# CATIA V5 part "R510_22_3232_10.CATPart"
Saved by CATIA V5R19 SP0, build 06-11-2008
Material "Steel": density 7860 kg/m3, Young's modulus 2e+11 Pa, Poisson ratio 0.266, thermal expansion 1.17e-05 1/K
Bounding box of the stored display mesh (mm): x -15.868 to 15.969, y -16.07 to 15.873, z 0 to 100
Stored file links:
  G:\Podręcznik\CD\Narzędzia\Arkusz Excel\Modele narzędzi\R510.22-3232-10.CATPart
  C:\Program Files\Dassault Systemes\B19\intel_a\startup\materials\Catalog.CATMaterial
  F:\OSTATNIE\DesignTable2.xls
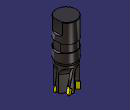
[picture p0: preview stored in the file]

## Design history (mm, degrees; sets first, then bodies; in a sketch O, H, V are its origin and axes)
Parameters
  CuttingType = "CUTTER"
  d = 32 mm {design table}
  D = 32 mm {design table}
  L = 100 mm {design table}
  l = 60 mm {design table}
  alfa = 11 deg {design table}
  gammap = 9 deg {design table}
  S = 3.18 mm {design table}
  epsilon = 85 deg {design table}
  lp = 10 mm {design table}
  x = 0.1131 mm {design table}
  gammaf = -12 deg {design table}
  z = 5 {design table}
  teta = 72 deg {design table}
  `lp'` = 9.8769 mm {design table}
  `lp''` = 5.8466 mm {design table}
Body1 "BODY" (main body), material "Steel"
  Sketch1 "sketch" on yz-plane, origin (0, 0, 0), H (0, 1, 0), V (0, 0, 1)
    line L1 (0, 2.0776) -> (15, 0.2358)
    line L2 (15, 0.2358) -> (15, 40)
    point P3 (15, 40)
    line L3 (15, 40) -> (15, 40)
    point P4 (16, 40)
    line L4 (16, 43.4583) -> (16, 58)
    point P5 (16, 58)
    line L5 (16, 58) -> (15, 58)
    line L6 (15, 58) -> (15, 70)
    line L7 (15, 70) -> (16, 70)
    point P8 (16, 70)
    line L8 (16, 70) -> (16, 99.2929)
    line L9 (16, 99.2929) -> (15.2929, 100)
    line L10 (15.2929, 100) -> (0, 100)
    point P11 (0, 100)
    line L11 (0, 100) -> (0, 2.0776)
    construction line L12 (0, -29.1199) -> (0, 199.3445)
    point P12 (0, -29.1199)
    construction line L13 (0, 0.1131) -> (16, 0.1131)
    point P14 (0, 0.1131)
    point P15 (16, 0.1131)
    construction line L14 (0, 2.0776) -> (16, 0.1131)
    axis line L15 (16, 0.1131) -> (16, -5.5625)
    line L16 (15, 40) -> (16, 43.4583)
    point P17 (15, 40)
    length L6 = 12 {= 0.2*l}
    distance P3 H = 40 {= L-l}
    length L9 = 1
    angle L8 L9 = 45
    distance L6 L8 = 1
    distance L8 L11 = 16 {= d/2}
    length L13 = 16 {= D/2}
    distance H L13 = 0.1131 {= x}
    distance L10 L7 = 30 {= 0.5*l}
    distance P15 L2 = 1
    distance P4 P5 = 18 {= 0.3*l}
    length L16 = 3.6 {= 0.2*(0.3*l)}
    angle L1 L2 = 83
    vertical: L2 V, L4 V, L6 V, L8 V, L11 V, L12 V, L15 V
    horizontal: L3 H, L5 H, L7 H, L10 H, L13 H
    coincidence: P8 L4, P11 V, P12 V, L1 L14, P14 L12, L3 P4, L4 P4, P3 P17
  Shaft1: profile Sketch1, axis Z axis, angle 360
  Fillet1: radius 1.6 {= 0.1*D/2}, on edge [face of Shaft1 from Sketch1.L1 | face of Shaft1 from Sketch1.L2]
  Sketch2 on zx-plane, origin (0, 0, 0), H (-1, 0, 0), V (0, 0, 1)
    line L1 (-14, 100) -> (-14, 82)
    line L2 (-14, 82) -> (-16, 80)
    line L3 (-16, 80) -> (-16, 72)
    line L4 (-16, 72) -> (-14, 70)
    point P5 (-14, 70)
    line L5 (-14, 70) -> (-14, 58)
    line L6 (-14, 58) -> (-16, 56)
    point P7 (-16, 56)
    line L7 (-16, 56) -> (-16, 56)
    line L8 (-16, 56) -> (-19, 56)
    line L9 (-19, 56) -> (-19, 100)
    line L10 (-19, 100) -> (-14, 100)
    reference projected line E1 through (0, 0) direction (0, 1) from axis of face of Shaft1 from Sketch1.L8
    reference projected line E2 (-9.2929, 100) -> (9.2929, 100) from edge [face of Shaft1 from Sketch1.L9 | face of Shaft1 from Sketch1.L10]
    distance L3 E1 = 16 {= d/2}
    distance L1 L3 = 2
    angle L2 L3 = 45
    angle L4 L3 = 45
    length L5 = 12 {= l*0.2}
    length L1 = 18 {= 0.3*l}
    distance P5 L10 = 30 {= 0.5*l}
    distance L9 L1 = 5
    distance L7 L5 = 2
    angle L5 L6 = 45
    vertical: L1 V, L3 V, L5 V, L7 V, L9 V
    horizontal: L8 H, L10 H
    coincidence: L10 E2, L1 L5, P7 L8
  Pocket1: profile Sketch2, direction (0, -1, 0), length 8, mirrored extent
  Plane1: type Angle, Angle 150, Direction Z axis, RefPlane yz-plane
  Plane2: type Offset, Offset 1, RefPlane Plane1, reversed
  Sketch3 "gammap_os_obrotu" on Plane2, origin (0.866, -0.5, 0), H (-0.5, -0.866, 0), V (0, 0, 1)
    line L1 (1.3076, 0) -> (-0.9434, 0)
    reference intersected line E1 through (0, 0) direction (-1, 0) from xy-plane
    horizontal: L1 H
    coincidence: E1 L1
  Plane3 "gammap": type Angle, Angle -9 {= -gammap}, Direction Sketch3, RefPlane Plane2
  Plane4: type Offset, Offset 0.5, RefPlane Plane3, reversed
  Sketch4 on Plane4, origin (1.2725, -0.7347, 0.2327), H (-0.5, -0.866, 0), V (-0.1355, 0.0782, 0.9877)
    line L1 (-16, -2.3223) -> (-16, 6.2448)
    distance V L1 = 16 {= D/2}
  Plane5 "gammaf": type Angle, Angle 12 {= -gammaf}, Direction Sketch4, RefPlane Plane4
  Plane6: type Offset, Offset 0.5, RefPlane Plane5
  Plane7: type Angle, Angle 90, Direction Sketch4, RefPlane Plane5
  Sketch5 on Plane7, origin (4.6982, 14.5939, -0.5486), H (0.9503, -0.3114, 0), V (0.0101, 0.0309, 0.9995)
    point P1 (4.8413, 0.5489)
    line L1 (4.8413, 0.5489) -> (1.6042, 0.6729)
    line L2 (1.6042, 0.6729) -> (0.2625, 9.3333)
    line L3 (0.2625, 9.3333) -> (3.3104, 10.431)
    line L4 (3.3104, 10.431) -> (4.8413, 0.5489)
    reference projected line E1 (5.1594, -1.5042) -> (3.8478, 6.9619) from Sketch4
    construction line L5 (3.3104, 10.431) -> (-1.5922, 9.6715)
    axis line L6 (4.8413, 0.5489) -> (1.1512, -0.0228)
    reference intersected line E2 through (-0.0001, 0.5489) direction (-1, 0) from xy-plane
    distance L2 L4 = 3.18 {= S}
    length L4 = 10 {= lp}
    angle L5 L3 = 11 {= alfa}
    angle L6 L1 = 11 {= alfa}
    coincidence: L4 E1, P1 E2
    perpendicularity: L5 L2
    parallelism: L6 L5
  Plane8: type Offset, Offset 16 {= D/2}, RefPlane Plane1, reversed
  Sketch6 on Plane8, origin (13.8564, -8, 0), H (-0.5, -0.866, 0), V (0, 0, 1)
    line L1 (-9.5247, -3) -> (-9.5247, 26.3474)
    arc A1 centre (-21.5247, 26.3474) radius 12 from (-9.5247, 26.3474) to (-16, 37) ccw
    point P4 (-16, 37)
    line L2 (-16, 37) -> (-16, -3)
    point P5 (-16, -3)
    line L3 (-16, -3) -> (-9.5247, -3)
    axis line L4 (-16, -3) -> (-9.5247, -2.4335)
    point P6 (-16, -3)
    point P7 (-9.5247, -2.4335)
    reference projected line E1 (-9, 40) -> (9, 40) from edge [face of Shaft1 from Sketch1.L2 | face of Shaft1 from Sketch1.L16]
    distance L2 V = 16 {= D/2}
    angle L4 L2 = 85 {= epsilon}
    distance E1 P4 = 3
    radius A1 = 12
    distance H L3 = 3
    length L4 = 6.5 {= 0.65*lp}
    vertical: L1 V, L2 V
    horizontal: L3 H
    tangency: L1 A1
    coincidence: P6 P5, P7 L1
  Pocket2: profile Sketch6, direction (-0.866, 0.5, 0), up to Plane6
  CircPattern1: of Pocket2, instances 5 {= z}, angular step 72 {= teta}, axis from Z axis
  Sketch7 on Plane5, origin (4.4973, -1.4261, 0.7803), H (-0.3066, -0.9518, 0), V (-0.1456, 0.0469, 0.9882)
    line L1 (-15.6327, 9.205) -> (-9.6759, 9.9244)
    point P1 (-15.6327, 9.205)
    reference projected point E1 (-15.6327, 9.205) from vertex [element of Sketch5 | element of Sketch5]
    reference projected line E2 (-15.2936, -1.0922) -> (-15.6227, 8.9024) from Sketch5.L4
    length L1 = 6 {= 0.6*lp}
    angle E2 L1 = 85 {= epsilon}
    coincidence: P1 E1
  Slot1: profile Sketch5, centre curve Sketch7
  CircPattern2: of Slot1, instances 5 {= z}, angular step 72 {= teta}, axis from Z axis
Body2 "INSERTS"
  Sketch8 "CUT" on yz-plane, origin (0, 0, 0), H (0, 1, 0), V (0, 0, 1)
    line L1 (10.1757, 0.5096) -> (16, 0)
    point P2 (16, 0)
    line L2 (16, 0) -> (16, 9.8769)
    line L3 (16, 9.8769) -> (10.1757, 10.3864)
    line L4 (10.1757, 10.3864) -> (10.1757, 0.5096)
    angle L3 L4 = 85
    length L2 = 9.8769 {= `lp'`}
    length L1 = 5.8466 {= `lp''`}
    distance L2 V = 16 {= D/2}
    vertical: L2 V, L4 V
    parallelism: L3 L1
    coincidence: P2 H
  Sketch9 "NOCUT" on yz-plane, origin (0, 0, 0), H (0, 1, 0), V (0, 0, 1)
    axis line L1 (16, 0) -> (0, 1.3998)
    point P1 (0, 1.3998)
    point P2 (16, 0)
    reference projected line E1 (4.0684, 1.0439) -> (10.0456, 0.5209) from Sketch8.L1
    reference projected point E2 (16, 0) from vertex [element of Sketch8 | element of Sketch8]
    line L2 (0, 1.3998) -> (10.1757, 0.5096)
    point P3 (10.1757, 0.5096)
    line L3 (10.1757, 0.5096) -> (10.1757, 10.3864)
    line L4 (10.1757, 10.3864) -> (15, 9.9644)
    line L5 (15, 9.9644) -> (15, 40)
    line L6 (15, 40) -> (16, 40)
    line L7 (16, 40) -> (16, 58)
    line L8 (16, 58) -> (15, 58)
    line L9 (15, 58) -> (15, 70)
    line L10 (15, 70) -> (16, 70)
    point P11 (16, 70)
    line L11 (16, 70) -> (16, 99.2929)
    point P12 (16, 100)
    line L12 (15.2929, 100) -> (0, 100)
    point P13 (0, 100)
    line L13 (0, 100) -> (0, 1.3998)
    line L14 (16, 99.2929) -> (15.2929, 100)
    length L9 = 12 {= 0.2*l}
    length L7 = 18 {= 0.3*l}
    distance L6 H = 40 {= L-l}
    distance L11 L13 = 16 {= d/2}
    distance L9 L11 = 1
    distance P3 P2 = 5.8466 {= `lp''`}
    distance L9 L7 = 1
    distance L5 P2 = 1
    length L3 = 9.8769 {= `lp'`}
    angle L10 L9 = 90
    distance P11 P12 = 30 {= 0.5*l}
    angle L11 L14 = 45
    length L14 = 1
    coincidence: P1 V, L1 E1, P2 E2, P13 V, L11 P12, L12 P12
    parallelism: L2 L1, L4 L1
    vertical: L3 V, L5 V, L7 V, L9 V, L11 V, L13 V
    horizontal: L6 H, L8 H, L12 H
  Sketch10 on Plane7, origin (4.6982, 14.5939, -0.5486), H (0.9503, -0.3114, 0), V (0.0101, 0.0309, 0.9995)
    point P1 (4.8413, 0.5489)
    line L1 (4.8413, 0.5489) -> (1.6042, 0.6729)
    line L2 (1.6042, 0.6729) -> (0.2625, 9.3333)
    line L3 (0.2625, 9.3333) -> (3.3104, 10.431)
    line L4 (3.3104, 10.431) -> (4.8413, 0.5489)
    reference intersected line E1 through (4.8039, 0.7908) direction (0.1531, -0.9882) from Plane5
    reference intersected line E2 through (-0.0001, 0.5489) direction (-1, 0) from xy-plane
    construction line L5 (3.3104, 10.431) -> (-7.5404, 8.75)
    axis line L6 (4.8413, 0.5489) -> (-1.7694, -0.4753)
    distance L2 L4 = 3.18 {= S}
    length L4 = 10 {= lp}
    angle L3 L5 = 11 {= alfa}
    angle L6 L1 = 11 {= alfa}
    coincidence: L4 E1, E2 P1
    perpendicularity: L5 L2
    parallelism: L6 L5
  Sketch11 on Plane5, origin (4.4973, -1.4261, 0.7803), H (-0.3066, -0.9518, 0), V (-0.1456, 0.0469, 0.9882)
    line L1 (-15.6327, 9.205) -> (-9.6759, 9.9244)
    point P1 (-15.6327, 9.205)
    reference projected point E1 (-15.6327, 9.205) from vertex [element of Sketch10 | element of Sketch10]
    reference projected line E2 (-15.3038, -0.7805) -> (-15.633, 9.2141) from Sketch10.L4
    angle L1 E2 = 85 {= epsilon}
    length L1 = 6 {= 0.6*lp}
    coincidence: P1 E1
  Rib1: profile Sketch10, centre curve Sketch11
  CircPattern3: of the body so far, instances 5 {= z}, angular step 72 {= teta}, axis from Z axis
  Sketch12 on face of Rib1, origin (0.1336, 0.2072, 1.976), H (0.8083, -0.5887, 0), V (-0.5842, -0.8021, 0.1239)
    point P1 (-0.1793, -15.9464)
    line L1 (-0.1793, -15.9464) -> (-3.0755, -14.3422)
    line L2 (-3.0755, -14.3422) -> (-3.2606, -14.9463)
    point P3 (-3.2606, -14.9463)
    line L3 (-3.2606, -14.9463) -> (-0.1793, -15.9464)
    reference projected point E1 (-0.1793, -15.9464) from vertex [face of Rib1 | face of Rib1 | face of Rib1]
    reference projected line E2 (-4.4655, -14.5552) -> (-1.3842, -15.5553) from edge [face of Rib1 | face of Rib1]
    reference projected point E3 (-3.2606, -14.9463) from vertex [face of Rib1 | face of Rib1 | face of Rib1]
    reference projected line E4 (-1.551, -9.3645) -> (0.2062, -3.6276) from edge [face of Rib1 | face of Rib1]
    angle L1 L3 = 11
    coincidence: E1 P1, L3 E2, P3 E3, L2 E4
  Pocket3: profile Sketch12, direction along edge [face of Rib1 | face of Rib1], length 10 {= lp}
  CircPattern4: of Pocket3, instances 5 {= z}, angular step 72 {= teta}, axis from Z axis
Relations
  design table, configuration 4, drives d, D, L, l, alfa, gammap, S, epsilon, lp, x, gammaf, z, teta, `lp'`, `lp''`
